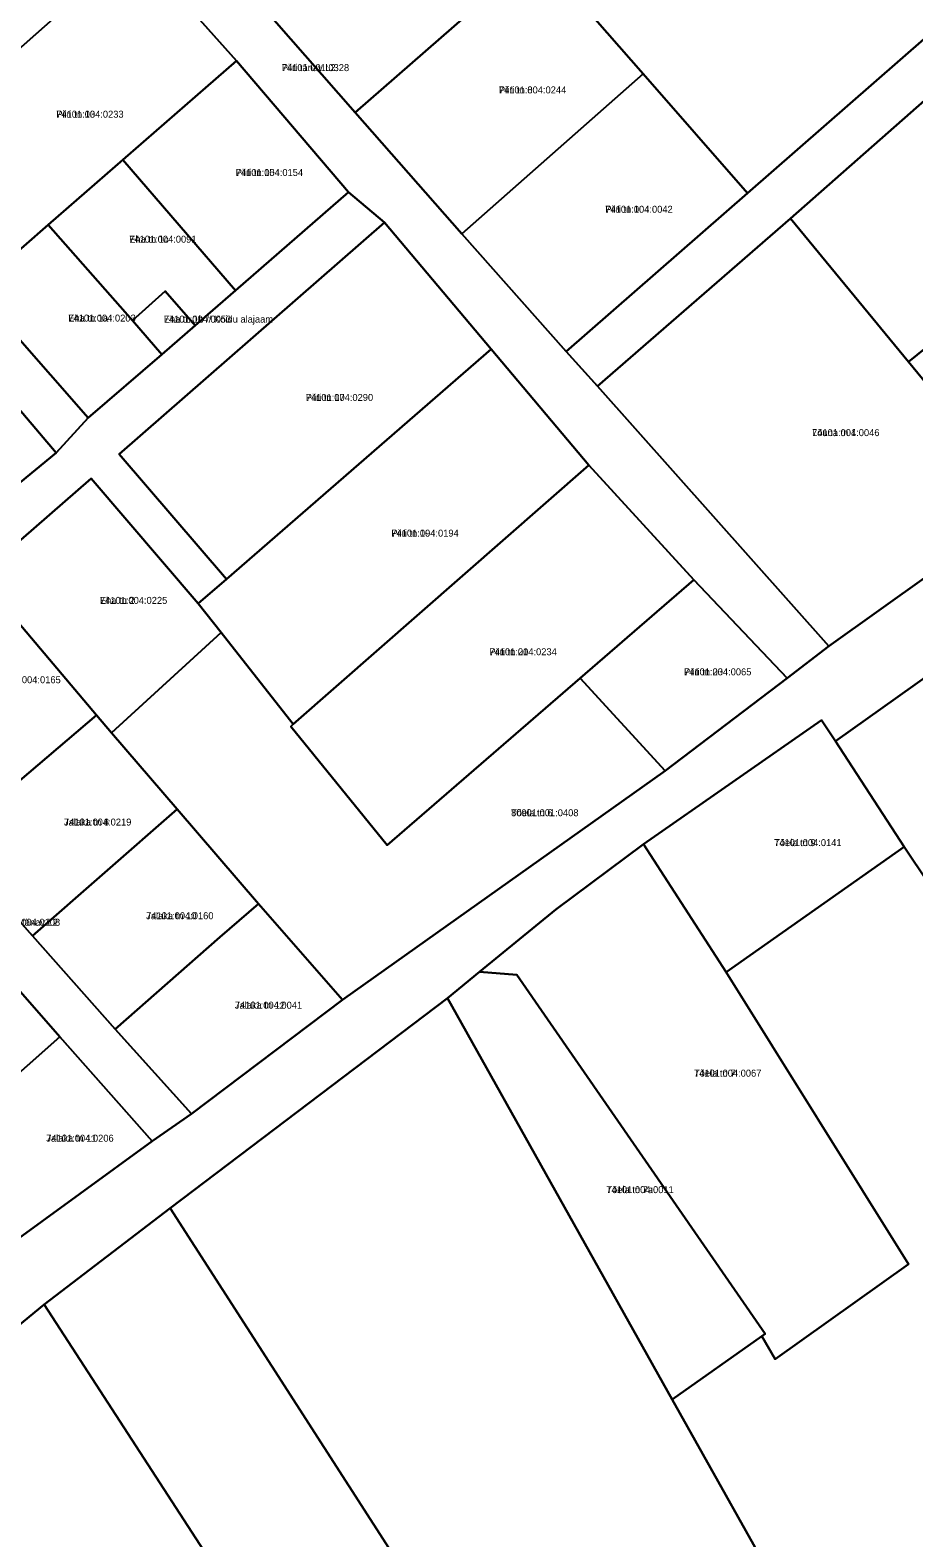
# Model space of a CAD drawing. Extents: x 524000 to 564260, y 6469338 to 6496391.
# Drawn here: x 538066.5 to 538256.7, y 6472932.3 to 6473256.9 of the extents above; entities that cross this region are included whole.
import ezdxf

# ---------------------------------------------------------------- set-up
doc = ezdxf.new("R2010")
doc.units = 0
for name, color, linetype in [('L_AADRESS', 7, 'Continuous'), ('PIIR', 7, 'Continuous'), ('TUNNUS', 7, 'Continuous')]:
    doc.layers.add(name, color=color, linetype=linetype)

msp = doc.modelspace()

# ---------------------------------------------------------------- linework, layer by layer
at = {"layer": 'PIIR'}
for points in [[(538002.94, 6473375.76), (538008.07, 6473386.14), (538009.78, 6473384.2), (538052.7, 6473335.3), (538060.31, 6473326.47), (538092.19, 6473289.93), (538111.88, 6473267.35), (538136.48, 6473239.23), (538159.4, 6473213.1), (538181.89, 6473187.71), (538188.63, 6473180.29), (538238.38, 6473124.26), (538229.44, 6473117.4), (538209.36, 6473138.59), (538186.75, 6473163.27), (538165.75, 6473188.27), (538142.79, 6473215.5), (538135.03, 6473222.08), (538110.95, 6473250.31), (538088.99, 6473274.96), (538066.93, 6473300.55), (538044.07, 6473327.05), (538010.97, 6473366.26)], [(538197.23, 6473337.27), (538239.21, 6473374.5), (538262.37, 6473349.06), (538284.96, 6473323.67), (538265.28, 6473306.25), (538241.96, 6473285.71), (538264.5, 6473259.96), (538220.9, 6473221.84), (538198.41, 6473247.54), (538175.67, 6473273.53), (538151.07, 6473301.61), (538142.21, 6473293.86), (538122.71, 6473316.4), (538137.81, 6473329.48), (538175.36, 6473362.86)], [(538287.83, 6473280.48), (538344.01, 6473329.89), (538350.51, 6473322.23), (538324.19, 6473299.2), (538295.84, 6473274.23), (538265.58, 6473247.6), (538230.14, 6473216.4), (538188.63, 6473180.29), (538181.89, 6473187.71), (538220.9, 6473221.84), (538264.5, 6473259.96)], [(538037.45, 6473274.84), (538066.93, 6473300.55), (538088.99, 6473274.96), (538033.3, 6473225.67), (538011.66, 6473251.45)], [(538175.67, 6473273.53), (538136.48, 6473239.23), (538111.88, 6473267.35), (538142.21, 6473293.86), (538151.07, 6473301.61)], [(537979.58, 6473287.68), (537992.9, 6473272.24), (538011.01, 6473251.05), (538011.66, 6473251.45), (538033.3, 6473225.67), (538054.58, 6473201.22), (538079, 6473173.43), (538072.12, 6473165.95), (538054.09, 6473187.1), (538042.21, 6473200.34), (538028.86, 6473215.53), (538003.68, 6473244.12), (537974.33, 6473277.57)], [(538033.3, 6473225.67), (538088.99, 6473274.96), (538110.95, 6473250.31), (538070.39, 6473215.01), (538054.58, 6473201.22)], [(538136.48, 6473239.23), (538175.67, 6473273.53), (538198.41, 6473247.54), (538159.4, 6473213.1)], [(538110.73, 6473200.91), (538086.47, 6473229.02), (538110.95, 6473250.31), (538135.03, 6473222.08)], [(538220.9, 6473221.84), (538181.89, 6473187.71), (538159.4, 6473213.1), (538198.41, 6473247.54)], [(538255.55, 6473185.53), (538230.14, 6473216.4), (538265.58, 6473247.6), (538294.22, 6473212.92), (538319.08, 6473182.6), (538301.16, 6473169.45), (538274.99, 6473201.26)], [(538086.47, 6473229.02), (538110.73, 6473200.91), (538102.01, 6473193.33), (538095.53, 6473200.73), (538088.51, 6473194.4), (538070.39, 6473215.01)], [(538054.58, 6473201.22), (538070.39, 6473215.01), (538088.51, 6473194.4), (538094.86, 6473187.09), (538079, 6473173.43)], [(538142.79, 6473215.5), (538165.75, 6473188.27), (538108.74, 6473138.7), (538085.64, 6473165.66)], [(538280.97, 6473154.63), (538238.38, 6473124.26), (538188.63, 6473180.29), (538230.14, 6473216.4), (538255.55, 6473185.53)], [(538274.99, 6473201.26), (538301.16, 6473169.45), (538280.97, 6473154.63), (538255.55, 6473185.53)], [(538019.42, 6473179.98), (538042.21, 6473200.34), (538054.09, 6473187.1), (538072.12, 6473165.95), (538047.81, 6473145.97), (538028.1, 6473168.59)], [(538102.01, 6473193.33), (538094.86, 6473187.09), (538088.51, 6473194.4), (538095.53, 6473200.73)], [(538254.62, 6473081.05), (538239.83, 6473103.82), (538280.11, 6473132.45), (538338.34, 6473041.35), (538356.88, 6473054.26), (538388.91, 6473076.57), (538364.49, 6473111.37), (538328.2, 6473166.67), (538364.75, 6473191.63), (538367.06, 6473188.32), (538648.17, 6472784.9), (538455.43, 6472781.14), (538407.66, 6472852.49)], [(538165.75, 6473188.27), (538186.75, 6473163.27), (538123.15, 6473107.48), (538107.59, 6473127.24), (538102.7, 6473133.45), (538108.74, 6473138.7)], [(538209.36, 6473138.59), (538184.89, 6473117.38), (538143.36, 6473081.4), (538122.6, 6473106.99), (538123.15, 6473107.48), (538186.75, 6473163.27)], [(538084.04, 6473105.65), (538080.82, 6473109.44), (538055.45, 6473139.33), (538079.61, 6473160.41), (538102.7, 6473133.45), (538107.59, 6473127.24)], [(538036.36, 6473122.66), (538055.45, 6473139.33), (538080.82, 6473109.44), (538061.82, 6473093.25)], [(538209.36, 6473138.59), (538229.44, 6473117.4), (538203.17, 6473097.43), (538184.89, 6473117.38)], [(538098.17, 6473089.18), (538084.04, 6473105.65), (538107.59, 6473127.24), (538123.15, 6473107.48), (538122.6, 6473106.99), (538143.36, 6473081.4), (538184.89, 6473117.38), (538203.17, 6473097.43), (538133.75, 6473048.11), (538115.64, 6473068.83)], [(538023.36, 6473111.35), (538049.28, 6473081.9), (538067.02, 6473061.88), (538084.82, 6473041.79), (538101.22, 6473023.61), (538092.79, 6473017.72), (538072.92, 6473040.16), (538053.81, 6473061.92), (538034.77, 6473083.64), (538015.7, 6473105.17)], [(538067.02, 6473061.88), (538049.28, 6473081.9), (538061.82, 6473093.25), (538080.82, 6473109.44), (538084.04, 6473105.65), (538098.17, 6473089.18)], [(538216.33, 6473054.12), (538198.52, 6473081.62), (538236.84, 6473108.34), (538239.83, 6473103.82), (538254.62, 6473081.05)], [(538098.17, 6473089.18), (538115.64, 6473068.83), (538107.36, 6473061.59), (538084.82, 6473041.79), (538067.02, 6473061.88)], [(538198.52, 6473081.62), (538216.33, 6473054.12), (538255.54, 6472991.23), (538226.87, 6472970.76), (538224, 6472975.7), (538224.71, 6472976.21), (538171.24, 6473053.5), (538163.25, 6473054.13), (538179.68, 6473067.6)], [(538254.62, 6473081.05), (538407.66, 6472852.49), (538381.66, 6472835.41), (538374.77, 6472836.59), (538368.09, 6472824.25), (538395.14, 6472779.98), (538307.73, 6472778.3), (538204.69, 6472962.04), (538224, 6472975.7), (538226.87, 6472970.76), (538255.54, 6472991.23), (538216.33, 6473054.12)], [(538101.22, 6473023.61), (538084.82, 6473041.79), (538107.36, 6473061.59), (538115.64, 6473068.83), (538133.75, 6473048.11)], [(538041.79, 6473017.16), (538024.81, 6473036.32), (538053.81, 6473061.92), (538072.92, 6473040.16), (538044.04, 6473014.64)], [(538163.25, 6473054.13), (538171.24, 6473053.5), (538224.71, 6472976.21), (538224, 6472975.7), (538204.69, 6472962.04), (538156.34, 6473048.5)], [(538156.34, 6473048.5), (538204.69, 6472962.04), (538307.73, 6472778.3), (538280.97, 6472777.95), (538239.16, 6472781.62), (538096.61, 6473003.26)], [(538044.04, 6473014.64), (538072.92, 6473040.16), (538092.79, 6473017.72), (538061.61, 6472995)], [(538096.61, 6473003.26), (538239.16, 6472781.62), (538197.42, 6472785.22), (538069.5, 6472982.51)], [(538063.82, 6472927.37), (538043.92, 6472961.49), (538069.5, 6472982.51), (538197.42, 6472785.22), (538167.63, 6472787.73), (538094.14, 6472794.44), (538052.97, 6472797.96), (538053.69, 6472807.94), (538096.61, 6472807.14), (538101.49, 6472803.54), (538148.19, 6472799.6), (538143.82, 6472806.23), (538125.46, 6472834.03), (538102.73, 6472867.87), (538080.43, 6472860.92), (538075.66, 6472867.92), (538096.35, 6472877.38), (538076.89, 6472907.52)]]:
    msp.add_lwpolyline(points, close=True, dxfattribs=at)
for points in [[(538047.81, 6473145.97), (538072.12, 6473165.95), (538079, 6473173.43), (538094.86, 6473187.09), (538102.01, 6473193.33), (538110.73, 6473200.91), (538135.03, 6473222.08), (538142.79, 6473215.5), (538085.64, 6473165.66), (538108.74, 6473138.7), (538102.7, 6473133.45), (538079.61, 6473160.41), (538055.45, 6473139.33)], [(537806.63, 6472920.9), (537804.19, 6472932.78), (537839.27, 6472939.13), (537868.93, 6472944.94), (537900.85, 6472949.96), (537922.62, 6472953.66), (537946.68, 6472957.74), (537977.99, 6472963.06), (538023.97, 6472971.06), (538035.34, 6472973.95), (538062.44, 6472994.07), (538061.61, 6472995), (538092.79, 6473017.72), (538101.22, 6473023.61), (538133.75, 6473048.11), (538203.17, 6473097.43), (538229.44, 6473117.4), (538238.38, 6473124.26), (538280.97, 6473154.63)], [(538280.11, 6473132.45), (538239.83, 6473103.82), (538236.84, 6473108.34), (538198.52, 6473081.62), (538179.68, 6473067.6), (538163.25, 6473054.13), (538156.34, 6473048.5), (538096.61, 6473003.26), (538069.5, 6472982.51), (538043.92, 6472961.49), (537982.1, 6472947.96), (537977.91, 6472947.2), (537953.06, 6472942.7), (537931.53, 6472938.68), (537908.79, 6472934.6), (537892.39, 6472931.98)]]:
    msp.add_lwpolyline(points, dxfattribs=at)

# ---------------------------------------------------------------- texts
at = {"layer": 'L_AADRESS'}
for s, p in [('Piiri tänav L2', (538120.66, 6473248.12)), ('Piiri tn 8', (538167.39, 6473243.32)), ('Piiri tn 13', (538072.12, 6473238.09)), ('Piiri tn 15', (538110.75, 6473225.53)), ('Piiri tn 10', (538190.3, 6473217.62)), ('Eha tn 1c', (538087.82, 6473211.17)), ('Eha tn 1a', (538074.72, 6473194.19)), ('Eha tn 1b // Koidu alajaam', (538095.26, 6473193.96)), ('Piiri tn 17', (538125.83, 6473177.1)), ('Lõuna tn 1', (538234.8, 6473169.52)), ('Piiri tn 19', (538144.25, 6473147.88)), ('Eha tn 2', (538081.52, 6473133.4)), ('Piiri tn 21', (538165.35, 6473122.33)), ('Piiri tn 23', (538207.24, 6473118.01)), ('Tõela tn 6', (538170.02, 6473087.67)), ('Jalaka tn 8', (538073.79, 6473085.66)), ('Tõela tn 9', (538226.64, 6473081.23)), ('Jalaka tänav L2', (538058.46, 6473064.08)), ('Jalaka tn 10', (538091.47, 6473065.49)), ('Jalaka tn 12', (538110.55, 6473046.22)), ('Tõela tn 7', (538209.39, 6473031.59)), ('Jalaka tn 11', (538069.98, 6473017.58)), ('Tõela tn 7a', (538190.53, 6473006.5))]:
    msp.add_text(s, height=1.5, dxfattribs=at).set_placement(p)
at = {"layer": 'TUNNUS'}
for s, p in [('74101:001:0328', (538120.66, 6473248.12)), ('74101:004:0244', (538167.39, 6473243.32)), ('74101:004:0233', (538072.12, 6473238.09)), ('74101:004:0154', (538110.75, 6473225.53)), ('74101:004:0042', (538190.3, 6473217.62)), ('74101:004:0091', (538087.82, 6473211.17)), ('74101:004:0203', (538074.72, 6473194.19)), ('74101:004:0053', (538095.26, 6473193.96)), ('74101:004:0290', (538125.83, 6473177.1)), ('74101:004:0046', (538234.8, 6473169.52)), ('74101:004:0194', (538144.25, 6473147.88)), ('74101:004:0225', (538081.52, 6473133.4)), ('74101:004:0234', (538165.35, 6473122.33)), ('74101:004:0165', (538058.59, 6473116.31)), ('74101:004:0065', (538207.24, 6473118.01)), ('80901:001:0408', (538170.02, 6473087.67)), ('74101:004:0219', (538073.79, 6473085.66)), ('74101:004:0141', (538226.64, 6473081.23)), ('74101:004:0108', (538058.46, 6473064.08)), ('74101:004:0160', (538091.47, 6473065.49)), ('74101:004:0041', (538110.55, 6473046.22)), ('74101:004:0067', (538209.39, 6473031.59)), ('74101:004:0206', (538069.98, 6473017.58)), ('74101:004:0011', (538190.53, 6473006.5))]:
    msp.add_text(s, height=1.5, dxfattribs=at).set_placement(p)

doc.saveas('drawing.dxf')
